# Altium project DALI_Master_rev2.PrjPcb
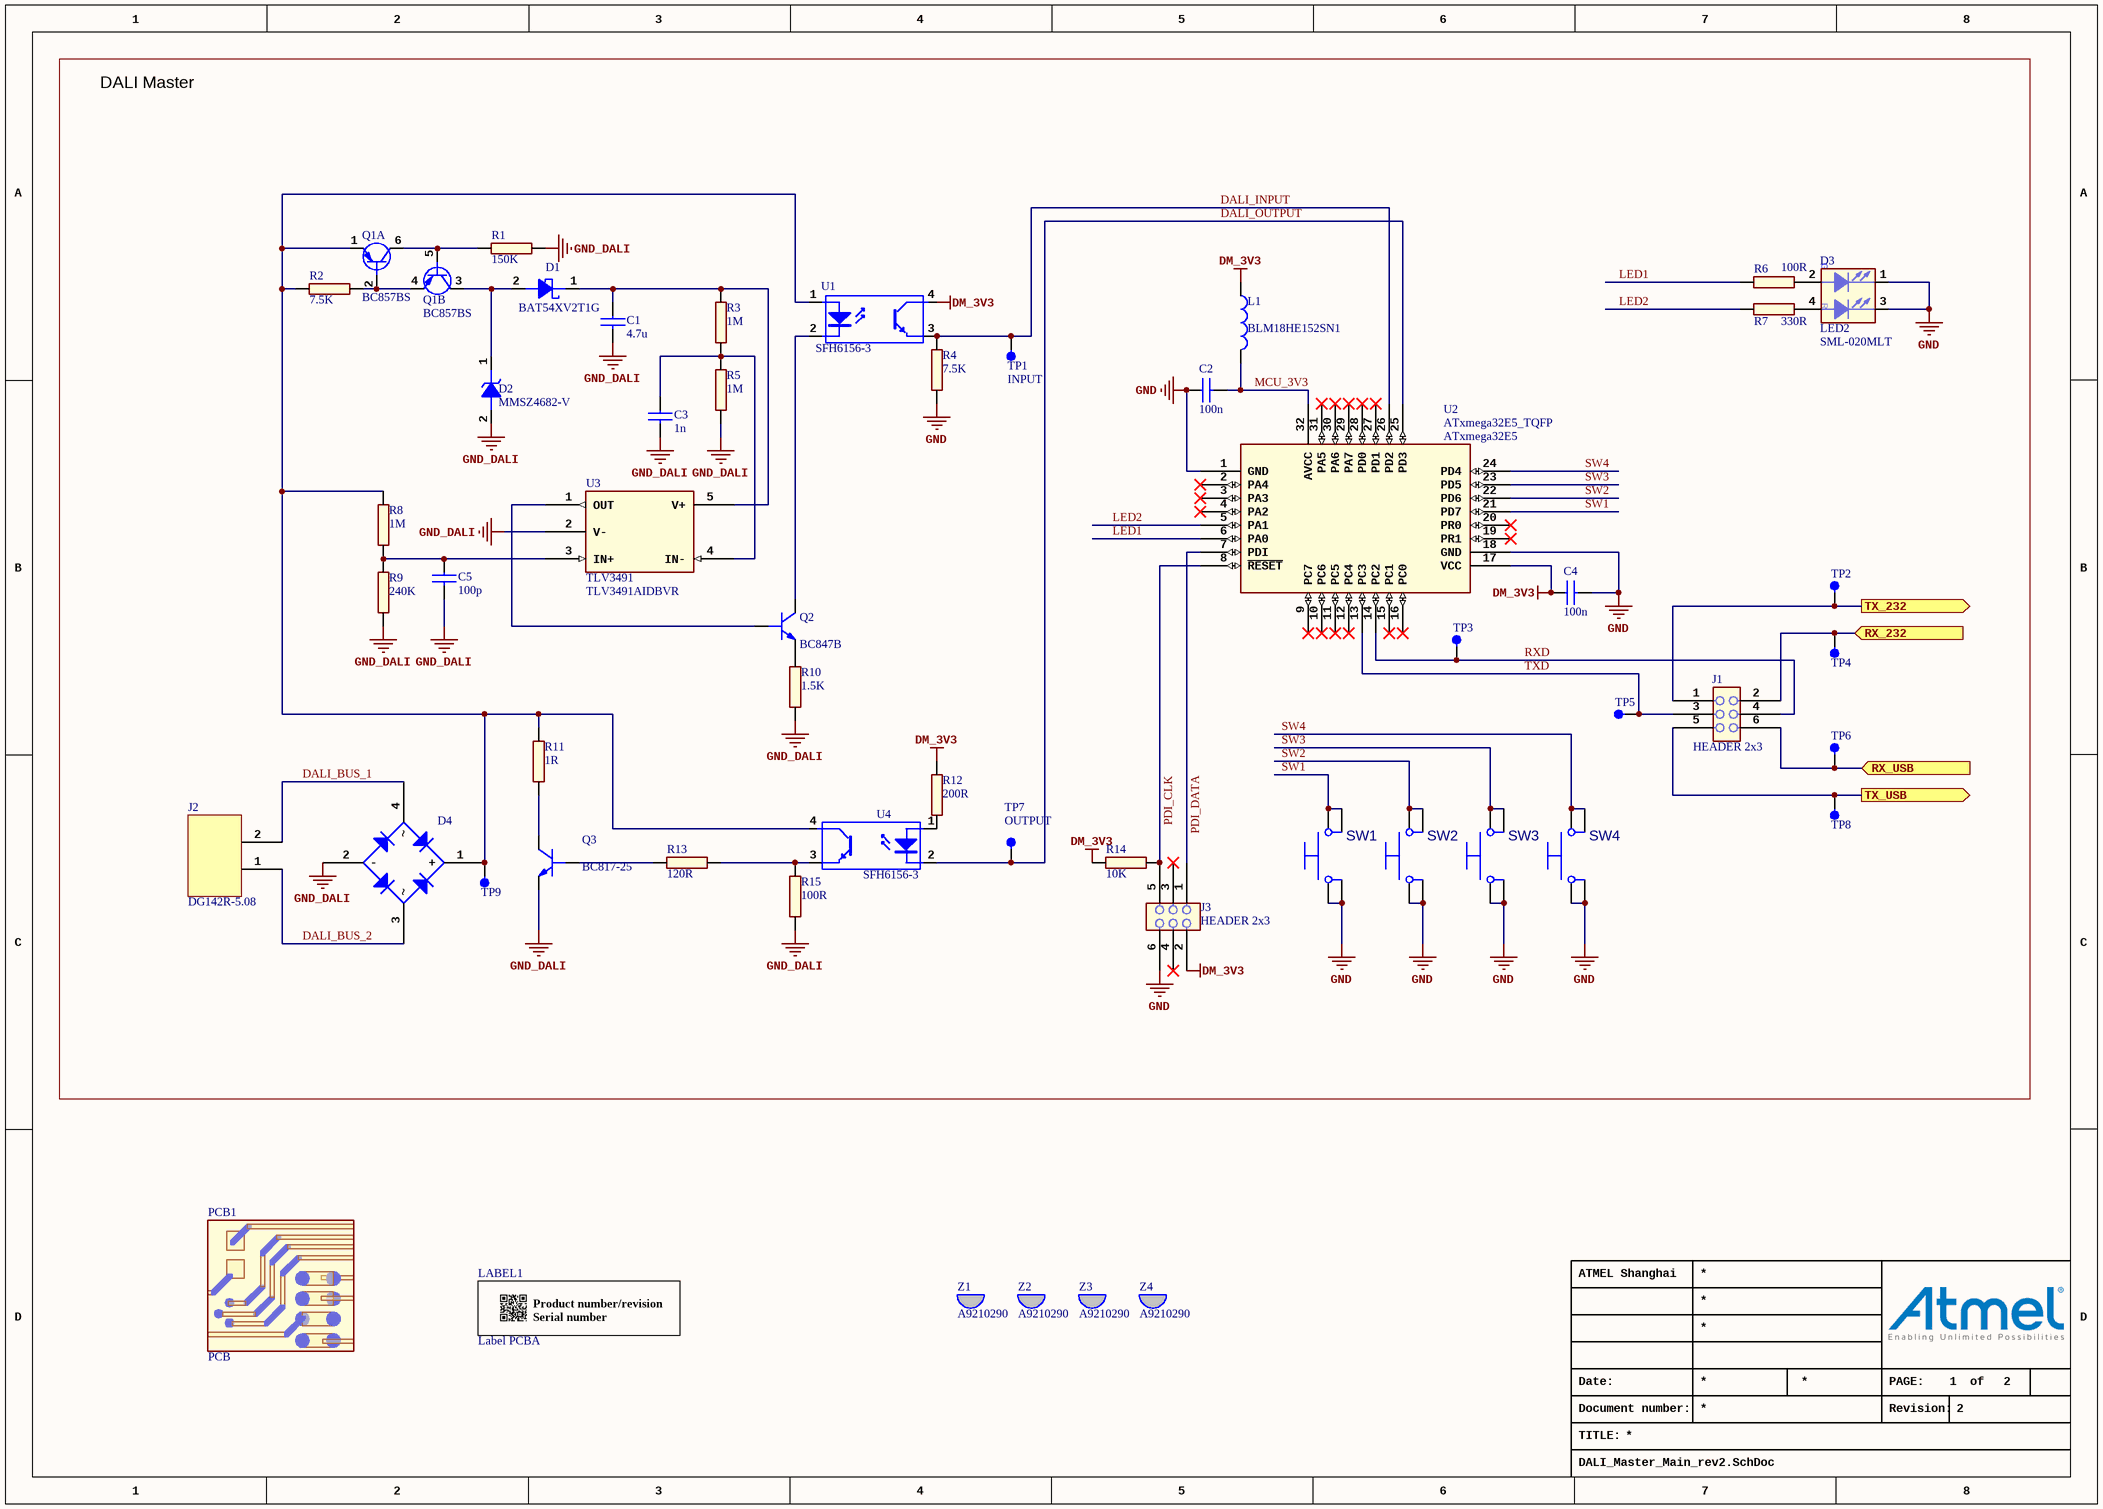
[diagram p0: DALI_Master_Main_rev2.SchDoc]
2 sheets, 98 parts. Net scope: global (net labels, ports and power ports of the same name join across sheets).
Board file: DALI_Master_rev2.PcbDoc
Sheets:
  DALI_Master_Main_rev2.SchDoc
  DALI_Master_Others_rev2.SchDoc

## Sheet DALI_Master_Main_rev2.SchDoc
size A3; Organization: ATMEL Shanghai; Revision: 2; SheetNumber: 1; SheetTotal: 2; Author: Tank Tang; PageSetup: Record=PageOptions|CenterHorizontal=True|CenterVertical=True|PrintScale=1.01|XCorrection=1.00|YCorrection=1.00|PrintKind=1|BorderSize=5000000|LeftOffset=0|BottomOffset=0|Orientation=2|PaperLength=1000|PaperWidth=1000|Scale=100|PaperSource=7|PrintQuality=-4|MediaType=1|DitherType=10|PaperKind=A3 (297 x 420 mm)|PrintScaleMode=1

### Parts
C1  value 4.7u  [AP1-00096]  (hidden comment: 1735527 @ element14)
C2  value 100n  [AP1-00096]  (hidden comment: 1828890 @ element14)
C3  value 1n  [AP1-00096]  (hidden comment: 8819955 @ element14)
C4  value 100n  [AP1-00096]  (hidden comment: 1828890 @ element14)
C5  value 100p  [AP1-00096]  (hidden comment: 8819866 @ element14)
D1  value BAT54XV2T1G  [AP4-00036]  (hidden comment: Farnell# 1615809)
D2  value MMSZ4682-V  [AP4-00012]  (hidden comment: ZENER_SMD_12)
D3  LED2  value SML-020MLT  [AP4-00030]
D4  DIODEBRIDGE  [AP4-00009]  (value not drawn)
J1  HEADER 2x3  [AP8-00182]
J2  value DG142R-5.08  [AP8-00788]  (hidden comment: Cable_connector_2Pin)
J3  HEADER 2x3  [AP8-00182]
L1  value BLM18HE152SN1  [AP3-00005]  (hidden comment: INDUCTOR)
LABEL1  Label PCBA  [AP8-00317]  (no BOM)
PCB1  PCB
Q1  value BC857BS  [AP5-00001]  (hidden comment: PNP DUAL)  (parts A,B of 2)
Q2  value BC847B  [AP5-00002]  (hidden comment: 1081232 @ element14)
Q3  value BC817-25  [AP5-00002]  (hidden comment: NPN BEC)
R1  value 150K  [AP2-00066]  (hidden comment: 9238743 @ element14)
R2  value 7.5K  [AP2-00066]  (hidden comment: 1799353 @ element14)
R3  value 1M  [AP2-00066]  (hidden comment: 9238840 @ element14)
R4  value 7.5K  [AP2-00066]  (hidden comment: 1799353 @ element14)
R5  value 1M  [AP2-00066]  (hidden comment: 9238840 @ element14)
R6  value 100R  [AP2-00066]  (hidden comment: 1255619 @element14)
R7  value 330R  [AP2-00066]  (hidden comment: 9238425 @element14)
R8  value 1M  [AP2-00066]  (hidden comment: 9238840 @ element14)
R9  value 240K  [AP2-00066]  (hidden comment: R2)
R10  value 1.5K  [AP2-00066]  (hidden comment: 9238506 @element14)
R11  value 1R  [AP2-00066]  (hidden comment: 9238123 @ element14)
R12  value 200R  [AP2-00066]  (hidden comment: 1799335 @ element14)
R13  value 120R  [AP2-00066]  (hidden comment: 9238379 @element14)
R14  value 10K  [AP2-00066]  (hidden comment: 9238603 @ element14)
R15  value 100R  [AP2-00066]  (hidden comment: 1255619 @element14)
SW1  B3S-1000P also can be used as MPN.Packaging difference only  [AP8-00481]  (value not drawn)  (no BOM)
SW2  B3S-1000P also can be used as MPN.Packaging difference only  [AP8-00481]  (value not drawn)  (no BOM)
SW3  B3S-1000P also can be used as MPN.Packaging difference only  [AP8-00481]  (value not drawn)  (no BOM)
SW4  B3S-1000P also can be used as MPN.Packaging difference only  [AP8-00481]  (value not drawn)  (no BOM)
TP1  INPUT  [AP8-00499]  (no BOM)
TP2  (no value)  [AP8-00499]  (no BOM)
TP3  (no value)  [AP8-00499]  (no BOM)
TP4  (no value)  [AP8-00499]  (no BOM)
TP5  (no value)  [AP8-00499]  (no BOM)
TP6  (no value)  [AP8-00499]  (no BOM)
TP7  OUTPUT  [AP8-00499]  (no BOM)
TP8  (no value)  [AP8-00499]  (no BOM)
TP9  (no value)  [AP8-00499]  (no BOM)
U1  value SFH6156-3  [AP6-00142]  (hidden comment: IS357)
U2  ATxmega32E5_TQFP  value ATxmega32E5  [AP6-00061]
U3  TLV3491  value TLV3491AIDBVR  [AP6-00087]
U4  value SFH6156-3  [AP6-00142]  (hidden comment: IS357)
Z1  value A9210290  [AP8-00414]  (hidden comment: Datasheet & Drawing in AP8-00414)
Z2  value A9210290  [AP8-00414]  (hidden comment: Datasheet & Drawing in AP8-00414)
Z3  value A9210290  [AP8-00414]  (hidden comment: Datasheet & Drawing in AP8-00414)
Z4  value A9210290  [AP8-00414]  (hidden comment: Datasheet & Drawing in AP8-00414)

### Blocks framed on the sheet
DALI Master: C1-C5 D1-D4 J1-J3 L1 Q1-Q3 R1-R15 SW1-SW4 TP1-TP9 U1-U4

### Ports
RX_232 (in), RX_USB (in), TX_232 (out), TX_USB (out)

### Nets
DM_3V3: C4.1 J3.2 L1.1 R12.2 R14.1 U1.4(C) U2.17(VCC)
GND: C2.1 C4.2 D3.1(CATHODE1) D3.3(CATHODE3) J3.6 R4.1 SW1.1 SW1.2 SW2.1 SW2.2 SW3.1 SW3.2 SW4.1 SW4.2 U2.1(GND) U2.18(GND)
GND_DALI: C1.2 C3.2 C5.2 D2.2(ANODE) D4.2(-) Q3.2(E) R1.2 R5.1 R9.1 R10.2 R15.1 U3.2(V-)
DALI_BUS_1: D4.4 J2.2
DALI_BUS_2: D4.3 J2.1
DALI_INPUT: R4.2 TP1.1 U1.3(GND) U2.26(PD2)
DALI_OUTPUT: TP7.1 U2.25(PD3) U4.2(K)
LED1: R6.1 U2.6(PA0)
LED2: R7.1 U2.5(PA1)
MCU_3V3: C2.2 L1.2 U2.32(AVCC)
PDI_CLK: J3.5 R14.2 U2.8(~{RESET})
PDI_DATA: J3.1 U2.7(PDI)
RX_232: J1.2 TP4.1 ; port RX_232
RX_USB: J1.6 TP6.1 ; port RX_USB
RXD: J1.4 TP3.1 U2.14(PC2)
SW1: SW1.3 SW1.4 U2.21(PD7)
SW2: SW2.3 SW2.4 U2.22(PD6)
SW3: SW3.3 SW3.4 U2.23(PD5)
SW4: SW4.3 SW4.4 U2.24(PD4)
TX_232: J1.1 TP2.1 ; port TX_232
TX_USB: J1.5 TP8.1 ; port TX_USB
TXD: J1.3 TP5.1 U2.13(PC3)
NetC1_1: C1.1 D1.1(CATHODE) R3.2 U3.5(V+)
NetC3_1: C3.1 R3.1 R5.2 U3.4(IN-)
NetC5_1: C5.1 R8.1 R9.2 U3.3(IN+)
NetD1_2: D1.2(ANODE) D2.1(CATHODE) Q1.3(C)
NetD3_2: D3.2(ANODE2) R6.2
NetD3_4: D3.4(ANODE4) R7.2
NetD4_1: D4.1(+) Q1.1(E) R2.1 R8.2 R11.2 TP9.1 U1.1(A) U4.4(C)
NetQ1_2: Q1.2(B) Q1.4(E) R2.2
NetQ1_5: Q1.5(B) Q1.6(C) R1.1
NetQ2_1: Q2.1(B) U3.1(OUT)
NetQ2_2: Q2.2(E) R10.1
NetQ2_3: Q2.3(C) U1.2(K)
NetQ3_1: Q3.1(B) R13.2
NetQ3_3: Q3.3(C) R11.1
NetR12_1: R12.1 U4.1(A)
NetR13_1: R13.1 R15.2 U4.3(GND)

Not connected (* = marked no-connect by the designer): J3 3* 4*; U2 2(PA4)* 3(PA3)* 4(PA2)* 9(PC7)* 10(PC6)* 11(PC5)* 12(PC4)* 15(PC1)* 16(PC0)* 19(PR1)* 20(PR0)* 27(PD1)* 28(PD0)* 29(PA7)* 30(PA6)* 31(PA5)*

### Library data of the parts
C1 = A01-0596: Ceramic capacitor, SMD 0603, X5R, 6.3V, ?0%; PartGroup: Capacitors,Ceramic,SMD 0603; Manufacturer: Murata; MPN: GRM188R60J475KE19D; TemperatureRange: -55 to +85; ComponentStatus: 'New (not verified)'
C2 C4 = A01-0597: Ceramic capacitor, SMD 0603, X7R, 16V, ?0%; PartGroup: Capacitors,Ceramic,SMD 0603; Manufacturer: Murata; MPN: GRM188R71C104KA01D; TemperatureRange: ?5 °C to +125 °C; ComponentStatus: 'New (not verified)'
C3 = A01-0598: Ceramic capacitor, SMD 0603, X7R, 50V, ?0%; PartGroup: Capacitors,Ceramic,SMD 0603; Manufacturer: Murata; MPN: GRM188R71H102KA01D; TemperatureRange: ?5 °C to +125 °C; ComponentStatus: 'New (not verified)'
C5 = A01-0599: Ceramic capacitor, SMD 0603, C0G, 50V, ?%; PartGroup: Capacitors,Ceramic,SMD 0603; Manufacturer: Murata; MPN: GRM1885C1H101JA01D; TemperatureRange: ?5 °C to +125 °C; ComponentStatus: 'New (not verified)'
D1 = A04-0049: Schottky diode, If:200mA, Vf:0.35V, Vrrm:30V, SOD-523; PartGroup: Diodes,Schottky; Manufacturer: ON Semiconductor; TemperatureRange: -55°C to +125°C; ComponentStatus: 'Active (verified)'
D2 = A04-0093: 2.7V 500mW SOD-123; PartGroup: Diodes,Zener; Manufacturer: vishay; TemperatureRange: -55 - 150 deg C; ComponentStatus: 'New (not verified)'
D3 = A10-0027: LED, 2 colour (RED/GREEN), transparent clear lens, SMD; PartGroup: Opto,LEDs,SMD; Manufacturer: ROHM; TemperatureRange: -30 - +85 deg C; ComponentStatus: 'Active (verified)'
D4 = A04-0007: SMD bridge rectifier, 1A, Vrrm=1k, Vrms=700, Vdc=1k; PartGroup: Diodes,Rectifier diodes,SMD bridge; Manufacturer: vishay; Value: DF10S-E3/77; TemperatureRange: -55 - +150 deg C; ComponentStatus: 'Active (verified)'
J1 J3 = A08-0006: 2x3 pin header, 2.54 mm pitch, Pin-in-Paste THM; PartGroup: Mechanical devices,Connectors,Pin headers; Value: CD075014 2X3; ComponentStatus: 'Active (verified)'
J2 = A08-1925: Cable connector, 2Pin, through-hole; PartGroup: Mechanical devices,Connectors,Other; ComponentStatus: 'New (not verified)'
L1 = A03-0036: SMD RF inductor 0603. Z=1500Ohm (@100MHz), Max R(dc)=0.50Ohm, Max current=500mA; PartGroup: Inductors,EMI; Manufacturer: Murata; Tolerance: ?5%; TemperatureRange: -55°C to +125°C; ComponentStatus: 'Active (verified)'
LABEL1 = A09-0611: PCBA identification label PP Top White Gloss; PartGroup: Mechanical devices,Packaging materials,Printed Labels; Manufacturer: ACT Logimark AS; MPN: 505462; ComponentStatus: 'Active (verified)'
PCB1 = A08-1927: DALI Master based on XmegaE5 PCB; PartGroup: Mechanical devices,Printed circuit boards; ComponentStatus: 'New (not verified)'
Q1 = A05-0037: General purpose SMD small signal BJT Dual transistor, 2xPNP. Body Sot363; PartGroup: Transistors,Small signal BJT,SMD; Manufacturer: Philips; TemperatureRange: -65 to +125 deg. C; ComponentStatus: 'Active (verified)'
Q2 = A05-0126: General purpose SMD small signal BJT transistor. Polarity:NPN, Body:SOT23, P(tot)=0.25W, V(ceo)=45V, I(c)=0.1A, h(fe)=200/450, f(t)=100MHz; PartGroup: Transistors,Small signal BJT,SMD; Manufacturer: NXP; TemperatureRange: -40 - +85 deg. C; ComponentStatus: 'New (not verified)'
Q3 = A05-0125: General purpose SMD small signal BJT transistor. Polarity:NPN, Body:SOT23,; PartGroup: Transistors,Small signal BJT,SMD; Manufacturer: NXP; TemperatureRange: -40 - +85 deg. C; ComponentStatus: 'New (not verified)'
R1 = A02-0815: SMD 0603, 1/10W, 1%; PartGroup: Resistors,SMD,0603 1%; Manufacturer: YAGEO CORP; MPN: RC0603FR-07150KL; TemperatureRange: ?5 °C to +155 °C; ComponentStatus: 'New (not verified)'
R2 R4 = A02-0814: SMD 0603, 1/10W, 1%; PartGroup: Resistors,SMD,0603 1%; Manufacturer: YAGEO CORP; MPN: RC0603FR-077K5L; TemperatureRange: ?5 °C to +155 °C; ComponentStatus: 'New (not verified)'
R3 R5 R8 = A02-0816: SMD 0603, 1/10W, 1%; PartGroup: Resistors,SMD,0603 1%; Manufacturer: YAGEO CORP; MPN: RC0603FR-071ML; TemperatureRange: ?5 °C to +155 °C; ComponentStatus: 'New (not verified)'
R6 R15 = A02-0819: SMD 0603, 1/10W, 1%; PartGroup: Resistors,SMD,0603 1%; Manufacturer: YAGEO CORP; MPN: RC0603FR-07100RL; TemperatureRange: ?5 °C to +155 °C; ComponentStatus: 'New (not verified)'
R7 = A02-0822: SMD 0603, 1/10W, 1%; PartGroup: Resistors,SMD,0603 1%; Manufacturer: YAGEO CORP; MPN: RC0603FR-07330RL; TemperatureRange: ?5 °C to +155 °C; ComponentStatus: 'New (not verified)'
R9 = A02-0817: SMD 0603, 1/10W, 1%; PartGroup: Resistors,SMD,0603 1%; Manufacturer: YAGEO CORP; MPN: RC0603FR-07240KL; TemperatureRange: ?5 °C to +155 °C; ComponentStatus: 'New (not verified)'
R10 = A02-0818: SMD 0603, 1/10W, 1%; PartGroup: Resistors,SMD,0603 1%; Manufacturer: YAGEO CORP; MPN: RC0603FR-071K5L; TemperatureRange: ?5 °C to +155 °C; ComponentStatus: 'New (not verified)'
R11 = A02-0825: SMD 0603, 1/10W, 1%; PartGroup: Resistors,SMD,0603 1%; Manufacturer: YAGEO CORP; MPN: RC0603FR-071RL; TemperatureRange: ?5 °C to +155 °C; ComponentStatus: 'New (not verified)'
R12 = A02-0826: SMD 0603, 1/10W, 1%; PartGroup: Resistors,SMD,0603 1%; Manufacturer: YAGEO CORP; MPN: RC0603FR-07200RL; TemperatureRange: ?5 °C to +155 °C; ComponentStatus: 'New (not verified)'
R13 = A02-0820: SMD 0603, 1/10W, 1%; PartGroup: Resistors,SMD,0603 1%; Manufacturer: YAGEO CORP; MPN: RC0603FR-07120RL; TemperatureRange: ?5 °C to +155 °C; ComponentStatus: 'New (not verified)'
R14 = A02-0821: SMD 0603, 1/10W, 1%; PartGroup: Resistors,SMD,0603 1%; Manufacturer: YAGEO CORP; MPN: RC0603FR-0710KL; TemperatureRange: ?5 °C to +155 °C; ComponentStatus: 'New (not verified)'
SW1-SW4 = A08-1855: Sealed Surface-mounting Tactile Switch; PartGroup: Mechanical devices,Switches,SMD; Manufacturer: Omron Components; ComponentStatus: 'Active (verified)'
TP1-TP9 = A08-1274: Single SMD testpad; PartGroup: Mechanical devices,Connectors,Test points; ComponentStatus: 'Active (verified)'
U1 U4 = A10-0103: Optocoupler, High Reliability, 5300 VRMS; PartGroup: Opto,Optocoupler,SMD; Manufacturer: vishay; TemperatureRange: - 55 °C to + 100 °C; ComponentStatus: 'New (not verified)'
U2 = A06-0854: AVR 8-bit RISC MCU TQFP32; PartGroup: Integrated Circuits,MCU, MPU, DSP,AVR MCU; Manufacturer: ATMEL; MPN: ATxmega32E5-AU; ComponentStatus: 'Active (verified)'
U3 = A06-0912: 1.8V, Nanopower, PUSH-PULL OUTPUT COMPARATOR,sot23-5; PartGroup: Integrated Circuits,General linear,Comparator; Manufacturer: Texas Instruments; TemperatureRange: ?0°C to +125°C; ComponentStatus: 'Active (verified)'
Z1-Z4 = A08-0977: adhesive PU Rubber foot, lucent, diam. 9.5mm height 3.8mm (de15815); PartGroup: Mechanical devices,Mounting accessories,Other; Manufacturer: OKW; TemperatureRange: -34 - +65 deg C; ComponentStatus: 'Active (verified)'

## Sheet DALI_Master_Others_rev2.SchDoc
size A3; Organization: ATMEL Shanghai; Revision: 2; SheetNumber: 2; SheetTotal: 2; Author: Tank Tang; PageSetup: Record=PageOptions|CenterHorizontal=True|CenterVertical=True|PrintScale=1.01|XCorrection=1.00|YCorrection=1.00|PrintKind=1|BorderSize=5000000|LeftOffset=0|BottomOffset=0|Orientation=2|PaperLength=1000|PaperWidth=1000|Scale=100|PaperSource=7|PrintQuality=-4|MediaType=1|DitherType=10|PaperKind=A3 (297 x 420 mm)|PrintScaleMode=1
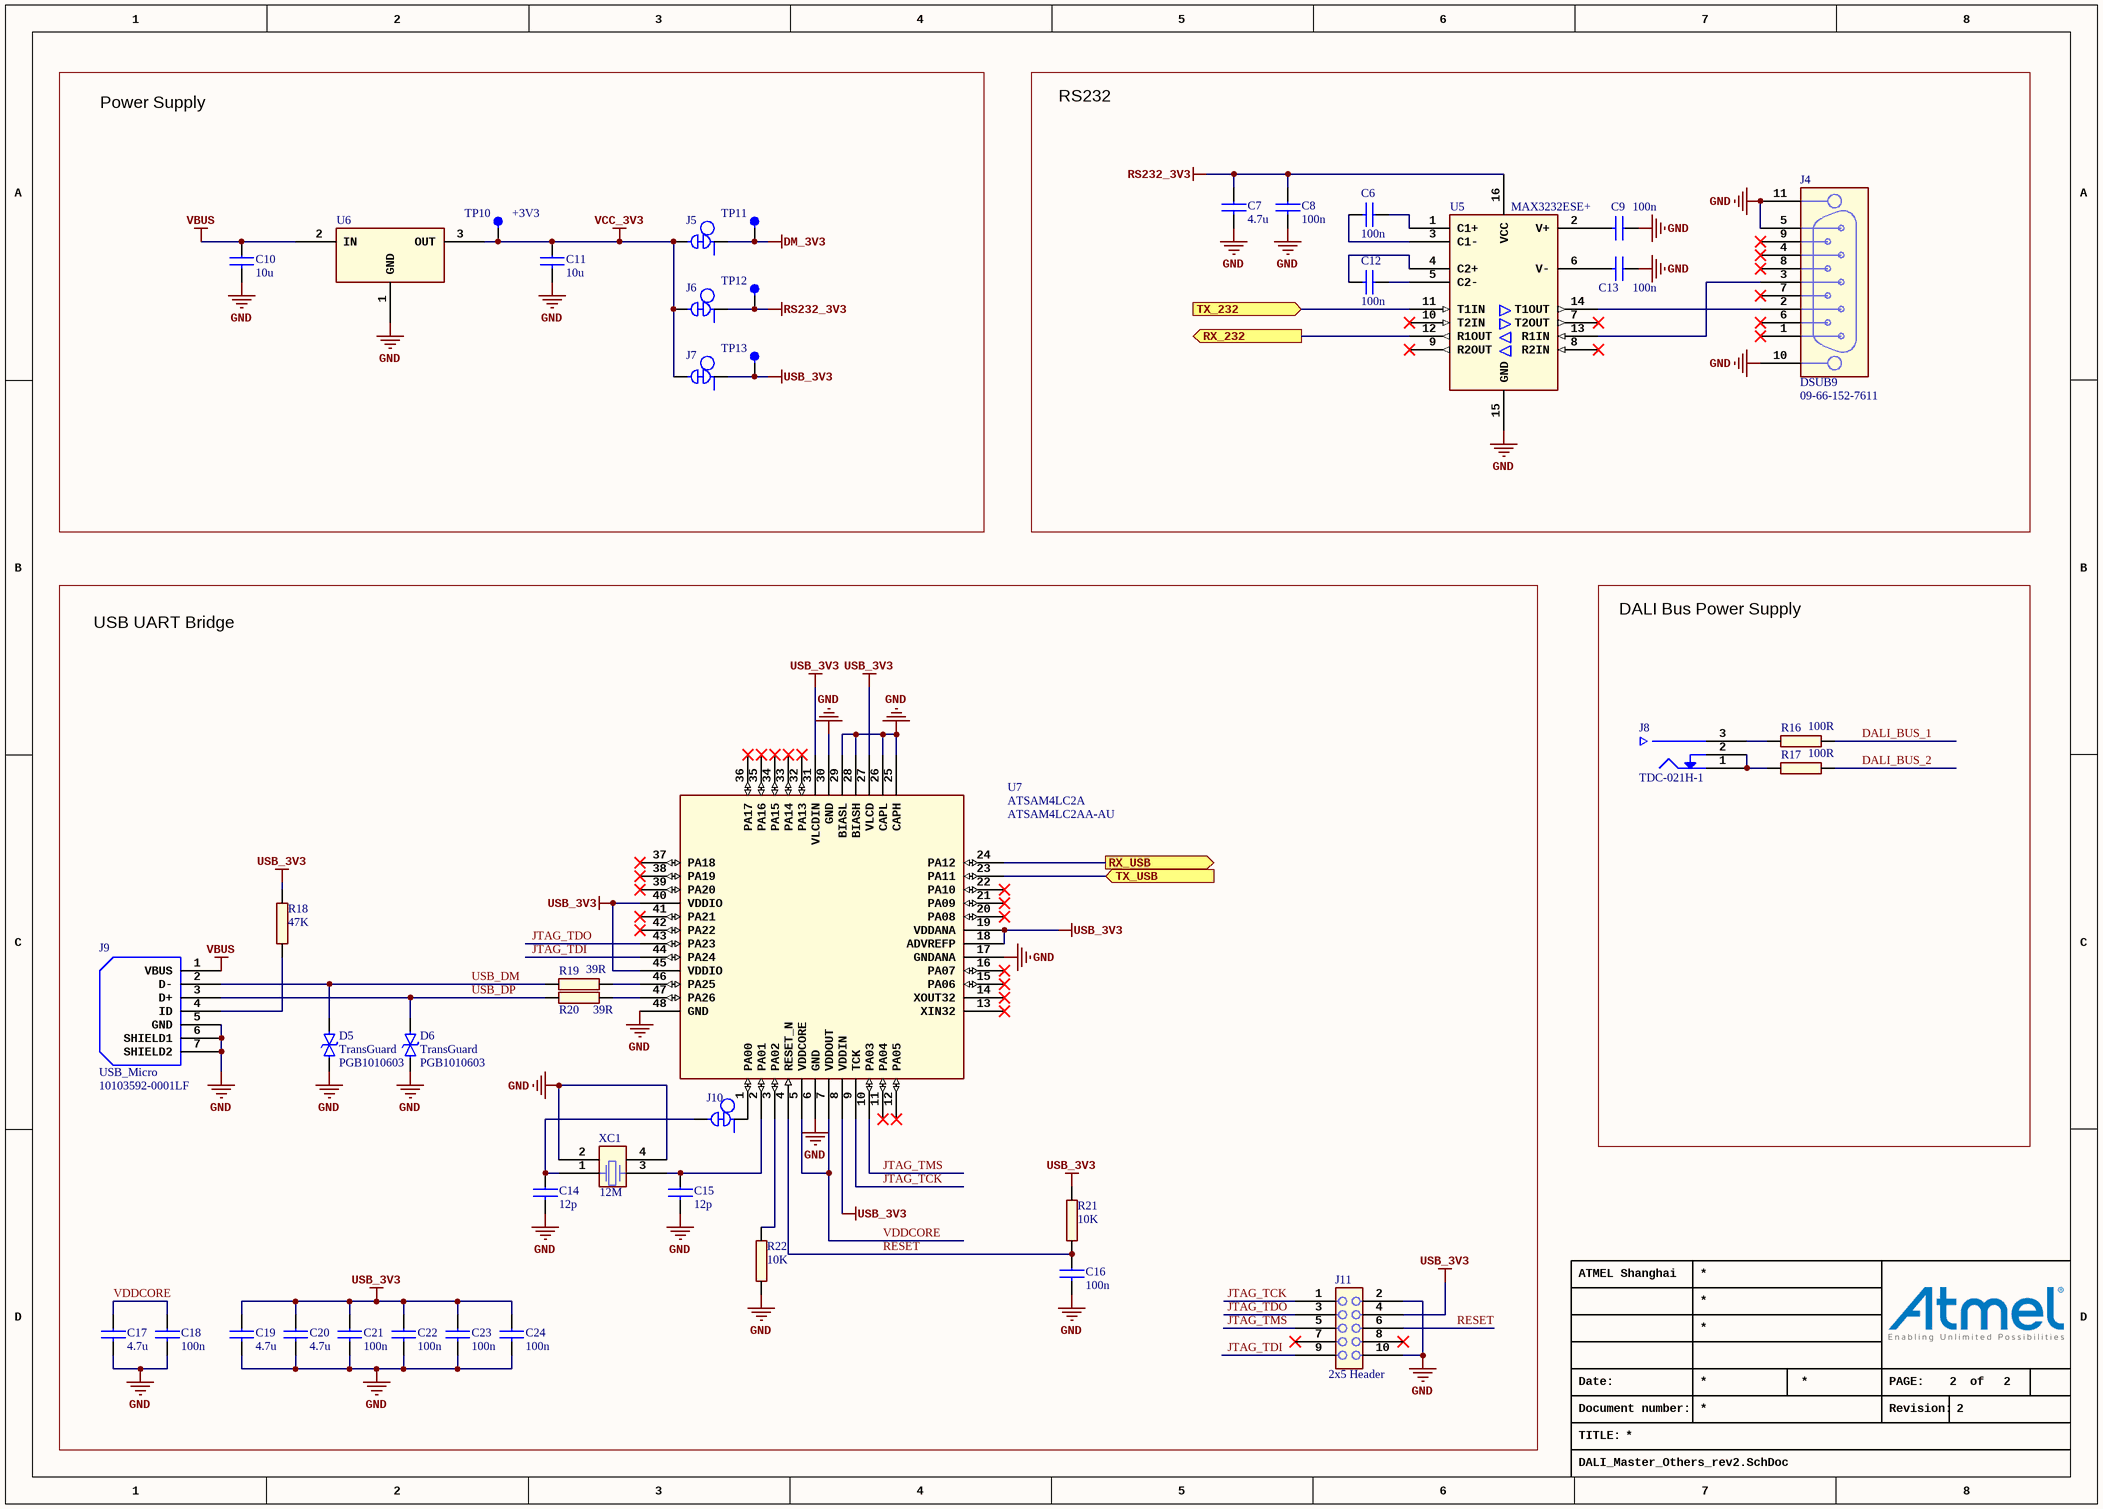
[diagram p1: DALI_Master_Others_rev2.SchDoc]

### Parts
C6  value 100n  [AP1-00096]  (hidden comment: 1828890 @ element14)  (no BOM)
C7  value 4.7u  [AP1-00096]  (hidden comment: 1735527 @ element14)  (no BOM)
C8  value 100n  [AP1-00096]  (hidden comment: 1828890 @ element14)  (no BOM)
C9  value 100n  [AP1-00096]  (hidden comment: 1828890 @ element14)  (no BOM)
C10  value 10u  [AP1-00097]  (hidden comment: 1889282 @ element14)
C11  value 10u  [AP1-00097]  (hidden comment: 1889282 @ element14)
C12  value 100n  [AP1-00096]  (hidden comment: 1828890 @ element14)  (no BOM)
C13  value 100n  [AP1-00096]  (hidden comment: 1828890 @ element14)  (no BOM)
C14  value 12p  [AP1-00096]  (hidden comment: 1828907 @ element14)
C15  value 12p  [AP1-00096]  (hidden comment: 1828907 @ element14)
C16  value 100n  [AP1-00096]  (hidden comment: 1828890 @ element14)
C17  value 4.7u  [AP1-00096]  (hidden comment: 1735527 @ element14)
C18  value 100n  [AP1-00096]  (hidden comment: 1828890 @ element14)
C19  value 4.7u  [AP1-00096]  (hidden comment: 1735527 @ element14)
C20  value 4.7u  [AP1-00096]  (hidden comment: 1735527 @ element14)
C21  value 100n  [AP1-00096]  (hidden comment: 1828890 @ element14)
C22  value 100n  [AP1-00096]  (hidden comment: 1828890 @ element14)
C23  value 100n  [AP1-00096]  (hidden comment: 1828890 @ element14)
C24  value 100n  [AP1-00096]  (hidden comment: 1828890 @ element14)
D5  TransGuard  value PGB1010603  [AP4-00024]
D6  TransGuard  value PGB1010603  [AP4-00024]
J4  DSUB9  value 09-66-152-7611  [AP8-00516]  (no BOM)
J5  SMD-STRAP_CLOSED  [AP9-00044]  (value not drawn)  (net tie, no BOM)
J6  SMD-STRAP_CLOSED  [AP9-00044]  (value not drawn)  (net tie, no BOM)
J7  SMD-STRAP_CLOSED  [AP9-00044]  (value not drawn)  (net tie, no BOM)
J8  value TDC-021H-1  [AP8-00017]  (hidden comment: Farnel #224959)
J9  USB_Micro  value 10103592-0001LF  [AP8-00610]
J10  SMD-STRAP_CLOSED  [AP9-00044]  (value not drawn)  (net tie, no BOM)
J11  2x5 Header  [AP8-00514]  (no BOM)
R16  value 100R  [AP2-00068]  (hidden comment: 1283115 @ element14)
R17  value 100R  [AP2-00068]  (hidden comment: 1283115 @ element14)
R18  value 47K  [AP2-00066]  (hidden comment: 9238689 @ element14)
R19  value 39R  [AP2-00066]  (hidden comment: 9238310 @ element14)
R20  value 39R  [AP2-00066]  (hidden comment: 9238310 @ element14)
R21  value 10K  [AP2-00066]  (hidden comment: 9238603 @ element14)
R22  value 10K  [AP2-00066]  (hidden comment: 9238603 @ element14)
TP10  +3V3  [AP8-00499]  (no BOM)
TP11  (no value)  [AP8-00499]  (no BOM)
TP12  (no value)  [AP8-00499]  (no BOM)
TP13  (no value)  [AP8-00499]  (no BOM)
U5  value MAX3232ESE+  [AP6-00122]  (hidden comment: MAX3232)  (no BOM)
U6  HT7533-2  [AP5-00036]  (value not drawn)
U7  ATSAM4LC2A  value ATSAM4LC2AA-AU  [AP6-00004]
XC1  value 12M  [AP7-00041]  (hidden comment: 1836841 @ element14)

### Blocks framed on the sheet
Power Supply: C10 C11 J5-J7 TP10-TP13 U6
RS232: C6-C9 C12 C13 J4 U5
USB UART Bridge: C14-C24 D5 D6 J9-J11 R18-R22 U7 XC1
DALI Bus Power Supply: J8 R16 R17

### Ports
RX_232 (out), RX_USB (out), TX_232 (in), TX_USB (in)

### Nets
DM_3V3: J5.1 TP11.1
GND: C7.2 C8.2 C9.1 C10.2 C11.2 C13.1 C14.2 C15.2 C16.2 C17.2 C18.2 C19.2 C20.2 C21.2 C22.2 C23.2 C24.2 D5.2 D6.2 J4.5 J4.10 J4.11 J9.5(GND) J9.6(SHIELD1) J9.7(SHIELD2) J11.2 J11.10 R22.1 U5.15(GND) U6.1(GND) U7.6(GND) U7.17(GNDANA) U7.25(CAPH) U7.26(CAPL) U7.28(BIASH) U7.29(BIASL) U7.30(GND) U7.48(GND) XC1.2 XC1.4
RS232_3V3: C7.1 C8.1 J6.1 TP12.1 U5.16(VCC)
USB_3V3: C19.1 C20.1 C21.1 C22.1 C23.1 C24.1 J7.1 J11.4 R18.2 R21.2 TP13.1 U7.8(VDDIN) U7.18(ADVREFP) U7.19(VDDANA) U7.27(VLCD) U7.31(VLCDIN) U7.40(VDDIO) U7.45(VDDIO)
VBUS: C10.1 J9.1(VBUS) U6.2(IN)
VCC_3V3: C11.1 J5.2 J6.2 J7.2 TP10.1 U6.3(OUT)
DALI_BUS_1: R16.2
DALI_BUS_2: R17.2
JTAG_TCK: J11.1 U7.9(TCK)
JTAG_TDI: J11.9 U7.44(PA24)
JTAG_TDO: J11.3 U7.43(PA23)
JTAG_TMS: J11.5 U7.10(PA03)
RESET: C16.1 J11.6 R21.1 U7.4(RESET_N)
RX_232: U5.12(R1OUT) ; port RX_232
RX_USB: U7.24(PA12) ; port RX_USB
TX_232: U5.11(T1IN) ; port TX_232
TX_USB: U7.23(PA11) ; port TX_USB
USB_DM: D5.1 J9.2(D-) R19.1
USB_DP: D6.1 J9.3(D+) R20.1
VDDCORE: C17.1 C18.1 U7.5(VDDCORE) U7.7(VDDOUT)
NetC6_1: C6.1 U5.1(C1+)
NetC6_2: C6.2 U5.3(C1-)
NetC9_2: C9.2 U5.2(V+)
NetC12_1: C12.1 U5.5(C2-)
NetC12_2: C12.2 U5.4(C2+)
NetC13_2: C13.2 U5.6(V-)
NetC14_1: C14.1 J10.2 XC1.1
NetC15_1: C15.1 U7.2(PA01) XC1.3
NetJ4_2: J4.2 U5.14(T1OUT)
NetJ4_3: J4.3 U5.13(R1IN)
NetJ8_1: J8.1 J8.2 R17.1
NetJ8_3: J8.3 R16.1
NetJ9_4: J9.4(ID) R18.1
NetJ10_1: J10.1 U7.1(PA00)
NetR19_2: R19.2 U7.46(PA25)
NetR20_2: R20.2 U7.47(PA26)
NetR22_2: R22.2 U7.3(PA02)

Not connected (* = marked no-connect by the designer): J4 1* 4* 6* 7* 8* 9*; J11 7* 8*; U5 7(T2OUT)* 8(R2IN)* 9(R2OUT)* 10(T2IN)*; U7 11(PA04)* 12(PA05)* 13(XIN32)* 14(XOUT32)* 15(PA06)* 16(PA07)* 20(PA08)* 21(PA09)* 22(PA10)* 32(PA13)* 33(PA14)* 34(PA15)* 35(PA16)* 36(PA17)* 37(PA18)* 38(PA19)* 39(PA20)* 41(PA21)* 42(PA22)*

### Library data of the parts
C6 C8 C9 C12 C13 C16 C18 C21-C24 = A01-0597: as C2 on sheet DALI_Master_Main_rev2
C7 C17 C19 C20 = A01-0596: as C1 on sheet DALI_Master_Main_rev2
C10 C11 = A01-0601: Ceramic capacitor, SMD 0805, X6S, 16V, ?0%; PartGroup: Capacitors,Ceramic,SMD 0805; Manufacturer: Murata; MPN: GRM21BC81C106KA73L; TemperatureRange: ?5 °C to +105 °C; ComponentStatus: 'New (not verified)'
C14 C15 = A01-0600: Ceramic capacitor, SMD 0603, C0G, 50V, ?%; PartGroup: Capacitors,Ceramic,SMD 0603; Manufacturer: Murata; MPN: GRM1885C1H120JA01D; TemperatureRange: ?5 °C to +125 °C; ComponentStatus: 'New (not verified)'
D5 D6 = A04-0018: ESD Suppressor; PartGroup: Diodes,Transient suppression; Manufacturer: Littelfuse; MPN: PGB1010603NR; TemperatureRange: -65c to +125C; ComponentStatus: 'Active (verified)'
J4 = A08-1327: DSUB9, right angle, THM (de2063); PartGroup: Mechanical devices,Connectors,DSUB; Manufacturer: Harting; ComponentStatus: 'Active (verified)'
J5-J7 J10 = A09-0783: Default closed SMD strap, 0603 size; PartGroup: Mechanical devices,PCB implemented components; Value: SMD-STRAP_0603_CLOSED; ComponentStatus: 'Active (verified)'
J8 = A08-0640: Through hole DC jack 2.1mm; PartGroup: Mechanical devices,Connectors,Power; Manufacturer: Technik Industrial Company; TemperatureRange: -25&#8451; to +85&#8451;; ComponentStatus: 'Active (verified)'
J9 = A08-1472: Micro USB B Connector; PartGroup: Mechanical devices,Connectors,USB; Manufacturer: FCI; ComponentStatus: 'Active (verified)'
J11 = A08-1323: 2x5 Header, SMD, Pitch1.27mm, Height4.68mm (de13733); PartGroup: Mechanical devices,Connectors,Pin headers; Value: M50_3600542; TemperatureRange: -40 deg C- +105 deg C; ComponentStatus: 'Active (verified)'
R16 R17 = A02-0831: SMD 2512, 1W, 1%; PartGroup: Resistors,SMD,2512 1%; Manufacturer: YAGEO CORP; MPN: RC2512FK-07100RL; TemperatureRange: â€?5 Â°C to +155 Â°C; ComponentStatus: 'New (not verified)'
R18 = A02-0827: SMD 0603, 1/10W, 1%; PartGroup: Resistors,SMD,0603 1%; Manufacturer: YAGEO CORP; MPN: RC0603FR-0747KL; TemperatureRange: ?5 °C to +155 °C; ComponentStatus: 'New (not verified)'
R19 R20 = A02-0823: SMD 0603, 1/10W, 1%; PartGroup: Resistors,SMD,0603 1%; Manufacturer: YAGEO CORP; MPN: RC0603FR-0739RL; TemperatureRange: ?5 °C to +155 °C; ComponentStatus: 'New (not verified)'
R21 R22 = A02-0821: as R14 on sheet DALI_Master_Main_rev2
TP10-TP13 = A08-1274: as TP1 on sheet DALI_Master_Main_rev2
U5 = A06-0733: RS-232 TRANSCEIVER, SO16, SMD (de21819); PartGroup: Integrated Circuits,Interface ICs,RS232; Manufacturer: Maxim; TemperatureRange: -40 deg C- +85 deg C; ComponentStatus: 'Active (verified)'
U6 = A06-1050: 100mA Low Power LDO; PartGroup: Integrated Circuits,Regulators,Linear; Manufacturer: Holtek; TemperatureRange: -40 to +85; ComponentStatus: 'New (not verified)'
U7 = A06-1043: 32-bit ARM MCU, SAM4L Series; PartGroup: Integrated Circuits,MCU, MPU, DSP,ARM MCU; Manufacturer: ATMEL; ComponentStatus: 'New (not verified)'; TemperatureRange: -40°C to +85°C
XC1 = A07-0096: 12MHz uXtal, 3.2 x 2.5 mm SMD, CL=18pF, 30PPM; PartGroup: Frequency devices,Crystals,SMD; Manufacturer: TXC Corporation; MPN: 7M-12.000MAAJ-T; TemperatureRange: -10 ~ +70 oC,; ComponentStatus: 'New (not verified)'

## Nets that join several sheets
DM_3V3: DALI_Master_Main_rev2 (7 pins), DALI_Master_Others_rev2 (J5.1 TP11.1)
GND: DALI_Master_Main_rev2 (16 pins), DALI_Master_Others_rev2 (40 pins)
DALI_BUS_1: DALI_Master_Main_rev2 (D4.4 J2.2), DALI_Master_Others_rev2 (R16.2)
DALI_BUS_2: DALI_Master_Main_rev2 (D4.3 J2.1), DALI_Master_Others_rev2 (R17.2)
RX_232: DALI_Master_Main_rev2 (J1.2 TP4.1), DALI_Master_Others_rev2 (U5.12)
RX_USB: DALI_Master_Main_rev2 (J1.6 TP6.1), DALI_Master_Others_rev2 (U7.24)
TX_232: DALI_Master_Main_rev2 (J1.1 TP2.1), DALI_Master_Others_rev2 (U5.11)
TX_USB: DALI_Master_Main_rev2 (J1.5 TP8.1), DALI_Master_Others_rev2 (U7.23)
